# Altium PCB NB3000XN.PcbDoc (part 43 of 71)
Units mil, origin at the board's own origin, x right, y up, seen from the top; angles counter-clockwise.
Board outline 9527.56 x 6929.77 mil, 6 copper layers (Top Layer, GND+SHIELD, MidLayer1, MidLayer2, P2 - 3V3+5V0, Bottom Layer), stack 62.375 mil thick; 832 components, 1027 nets, 4655 pads, 4981 vias.
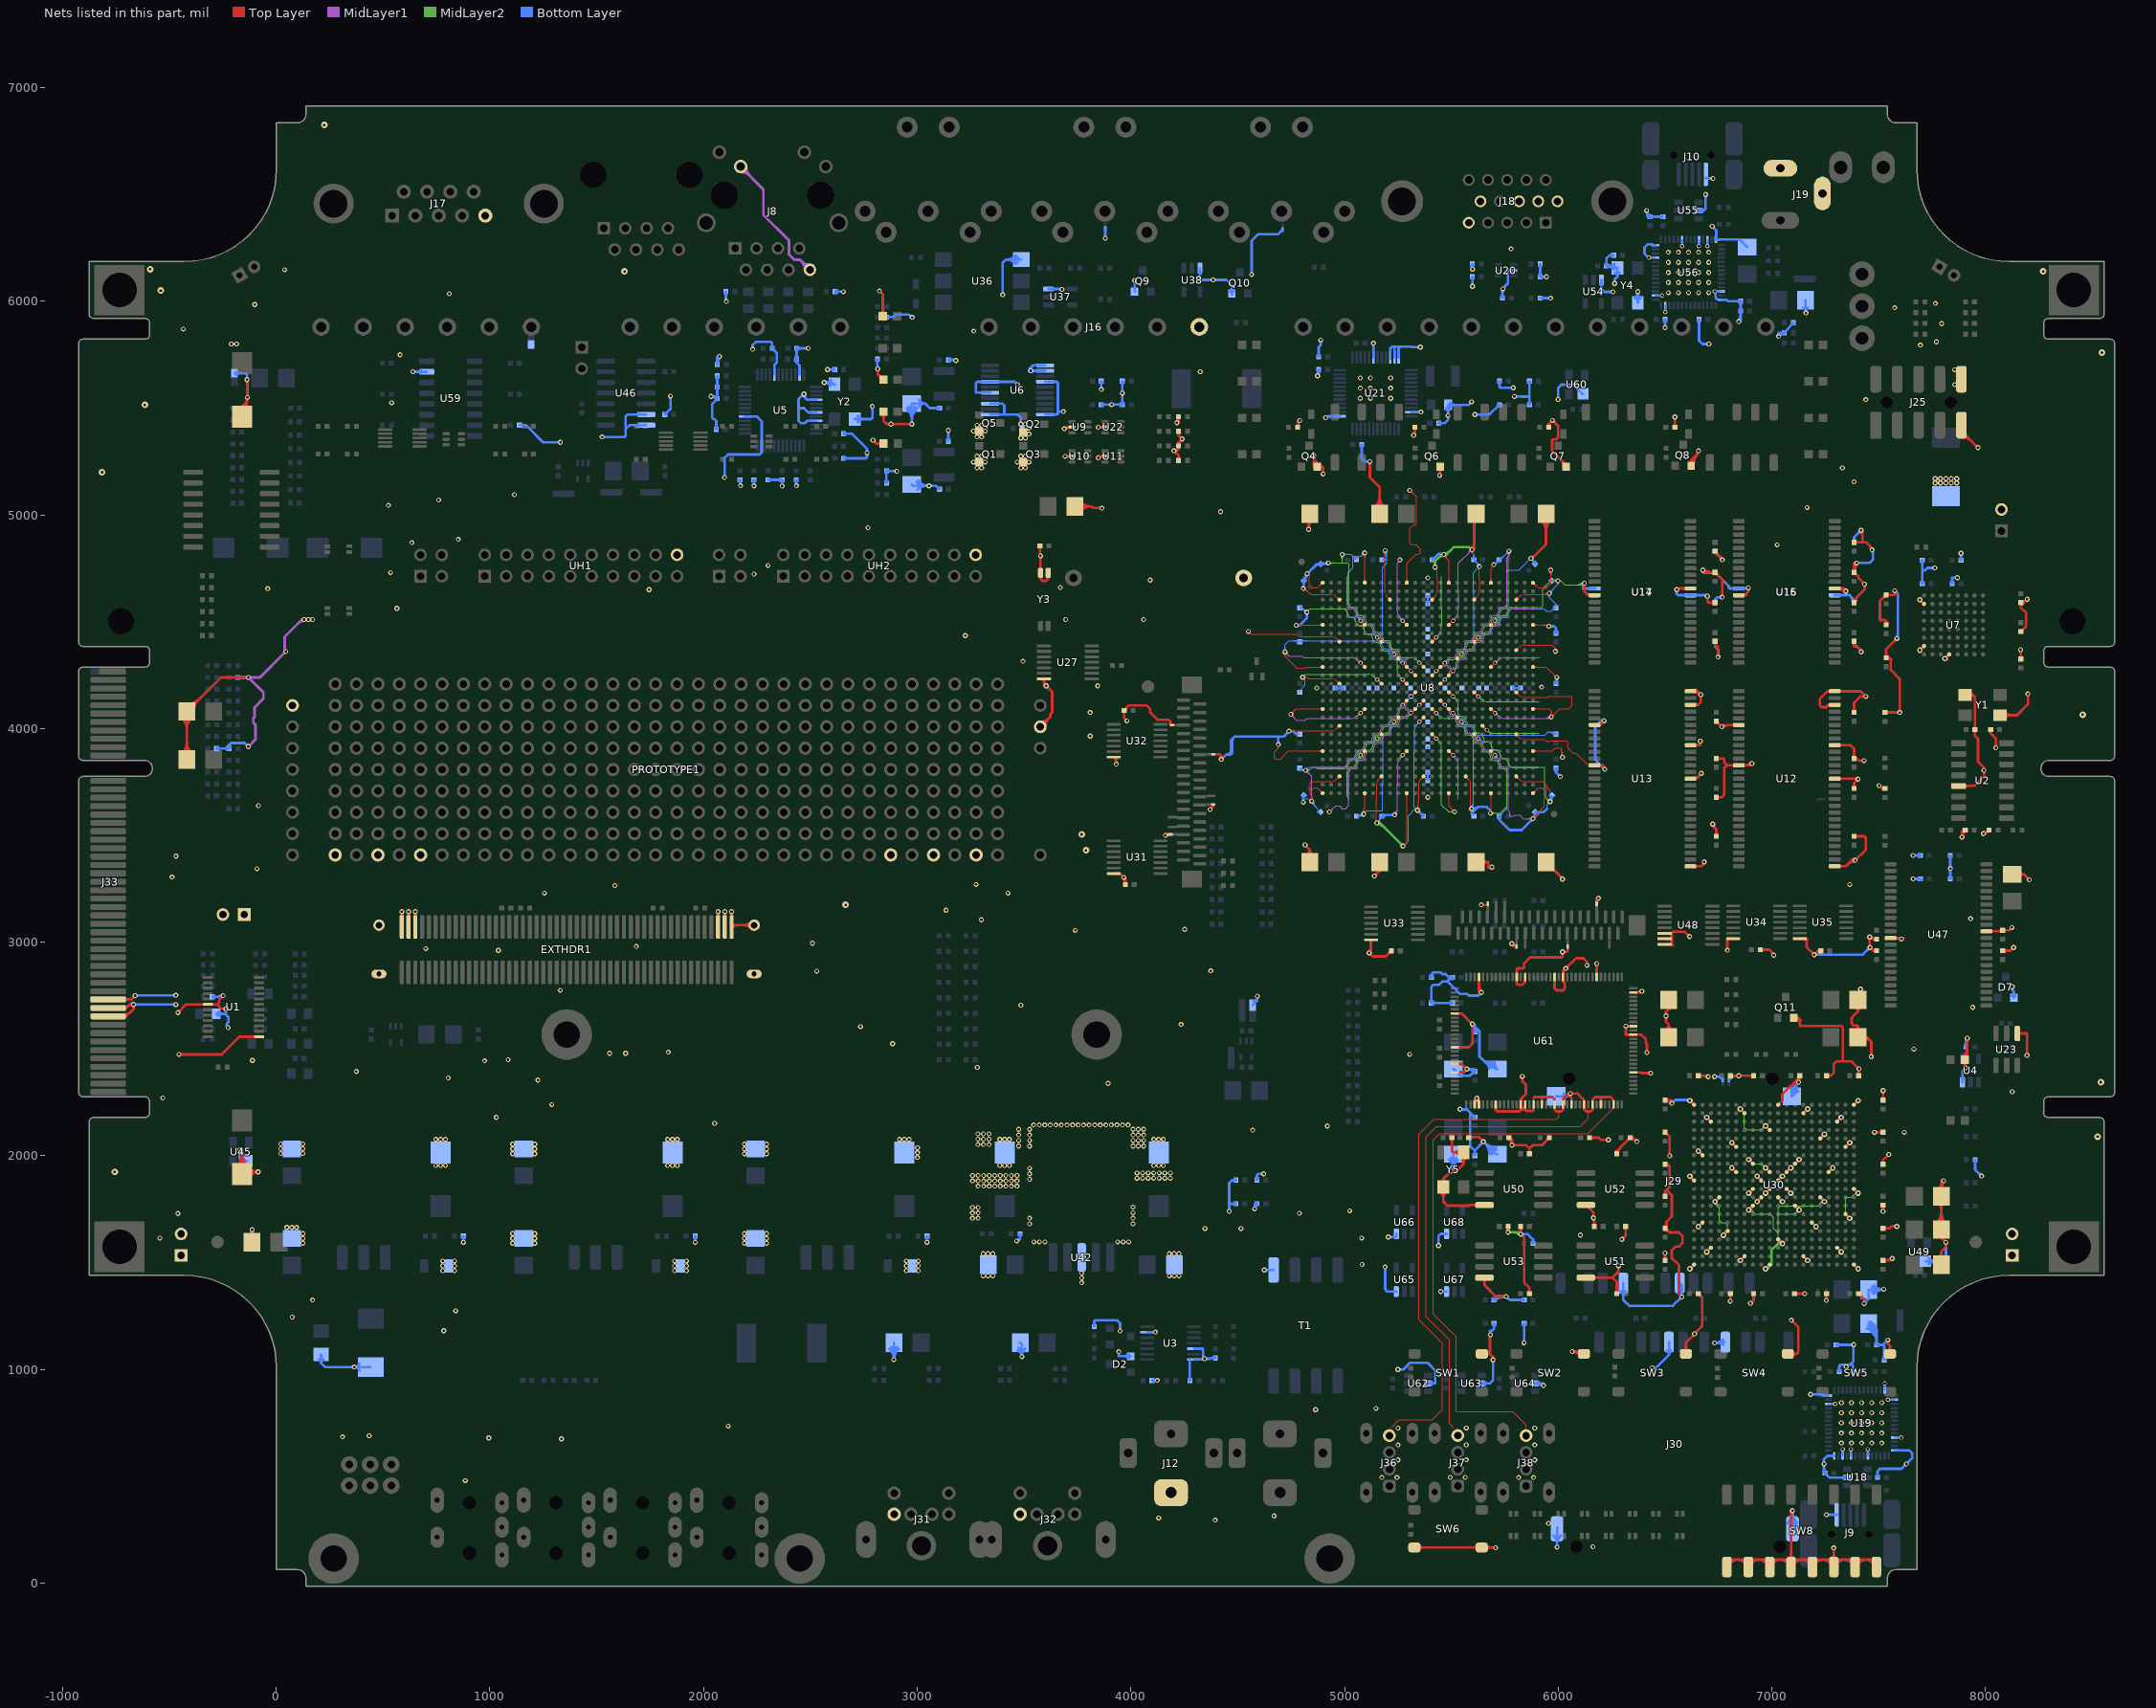
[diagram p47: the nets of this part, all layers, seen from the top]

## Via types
v1: diameter 23, hole 11.81, Top Layer to Bottom Layer, 3672 vias
v2: diameter 26, hole 11.81, Top Layer to Bottom Layer, 461 vias
v3: diameter 19, hole 11.81, Top Layer to Bottom Layer, tented both sides, 396 vias
v4: diameter 23.62, hole 11.81, Top Layer to Bottom Layer, 288 vias
v5: diameter 20, hole 11.81, Top Layer to Bottom Layer, 91 vias
v6: diameter 23, hole 11.81, Top Layer to Bottom Layer, tented both sides, 50 vias
v7: diameter 31, hole 11.81, Top Layer to Bottom Layer, 15 vias
v8: diameter 27.56, hole 11.81, Top Layer to Bottom Layer, tented both sides, 4 vias
v9: diameter 29, hole 11.81, Top Layer to Bottom Layer, 3 vias
v10: diameter 21, hole 11.81, Top Layer to Bottom Layer, 1 vias

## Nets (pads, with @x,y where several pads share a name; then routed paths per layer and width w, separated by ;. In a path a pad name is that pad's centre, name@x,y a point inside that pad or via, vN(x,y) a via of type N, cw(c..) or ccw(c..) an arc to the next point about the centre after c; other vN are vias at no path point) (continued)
GND: (continued)
  Top Layer w12: v1@7428.36,4676.04 ccw(c7415.08,4676.04) 7424.47,4685.43 ccw(c7433.86,4694.82) v1@7433.86,4681.54 ; 7428.54,110.71 cw(c7428.54,40.04) SW8.8@7478.51,90.01 ; v1@7429.97,4672.15 cw(c7420.58,4662.76) 7433.86,4662.76 cw(c7447.14,4662.76) v1@7437.75,4672.15 ; 7430.75,4159.56 cw(c7421.23,4150.04) v1@7434.69,4150.04 ; 7430.93,4159.38 ccw(c7440.19,4168.64) v1@7440.19,4155.54 ; C201.2@7435.5,2547.45 cw(c7445,2545.25) 7445,2555 ; C201.2@7435.5,2562.55 ccw(c7445,2564.75) 7445,2555 ; v1@7436.3,4146.15 ccw(c7426.91,4136.76) 7426.91,4150.04 ccw(c7426.91,4163.32) v1@7436.3,4153.93 ; v1@7453.64,3020.49 cw(c7444.25,3011.1) 7457.52,3011.1 cw(c7470.8,3011.1) v1@7461.41,3020.49 ; 7454.4,4859.83 cw(c7431.17,4836.6) v1@7464.02,4836.6 ; 7457.51,110.71 cw(c7457.51,69.01) SW8.8@7487,98.5 ; 7457.52,2992.34 ccw(c7476.49,2992.34) v1@7463.08,2978.93 ; v1@7457.73,3018.88 cw(c7458.78,2990.3) C156.2@7479,3010.52 ; v1@7461.3,2468.6 ccw(c7451.91,2477.99) 7465.19,2477.99 ccw(c7478.47,2477.99) v1@7469.08,2468.6 ; v1(7465.19,2464.71) 7465.19,2534.81 7445,2555 ; v1@7465.19,3024.33 7475.19,3014.33 C156.2@7490,3014.33 ; v1@7465.19,3024.37 v1(7457.52,3024.37) 7457.52,2976.71 v1(7459.19,2975.04) 7463.52,2975.04 7465.19,2973.37 7465.19,2969 7473.52,2960.67 C155.2@7490,2960.67 ; v1(7469.52,4836.6) 7469.52,4844.71 7442.86,4871.37 7423.52,4871.37 ; v4(7480,2110) 7479.33,2110.67 7480,2110.67 C234.2@7520,2110.67 ; v4@7484.11,2105.89 cw(c7495.64,2094.36) 7495.64,2110.67 ; v4@7484.11,2114.11 ccw(c7492.41,2122.41) 7492.41,2110.67 ; C155.2@7485.89,2956.56 ccw(c7475.97,2946.64) 7475.97,2960.67 ccw(c7475.97,2974.7) C155.2@7485.89,2964.78 ; C156.2@7485.89,3010.22 ccw(c7475.97,3000.3) 7475.97,3014.33 ccw(c7475.97,3028.36) C156.2@7485.89,3018.44 ; SW8.8@7490,110.71 7390,110.71 SW8.6@7290,110.71 ; v1(7501.86,3733.37) v1@7505.19,3730.04 ; v1@7505.19,3729.96 7515.19,3719.96 R157.1@7530,3719.96 ; v4@7515.89,1744.11 ccw(c7505.97,1754.03) 7520,1754.03 ccw(c7534.03,1754.03) v4@7524.11,1744.11 ; C195.2@7515.89,1765.22 cw(c7505.97,1755.3) 7520,1755.3 cw(c7534.03,1755.3) C195.2@7524.11,1765.22 ; C194.2@7515.89,1964.78 ccw(c7505.97,1974.7) 7520,1974.7 ccw(c7534.03,1974.7) C194.2@7524.11,1964.78 ; C234.2@7515.89,2106.56 ccw(c7505.97,2096.64) 7505.97,2110.67 ccw(c7505.97,2124.7) C234.2@7515.89,2114.78 ; C218.2@7515.89,2264.78 ccw(c7505.97,2274.7) 7520,2274.7 ccw(c7534.03,2274.7) C218.2@7524.11,2264.78 ; v4@7515.89,2300.89 cw(c7505.97,2290.97) 7520,2290.97 cw(c7534.03,2290.97) v4@7524.11,2300.89 ; C236.2@7520,1510.67 7554.82,1510.67 v1(7563.52,1519.37) ; C220.2@7520,1660.67 7549.98,1660.67 7559.31,1670 v4(7585,1670) ; v4(7520,1740) C195.2@7520,1769.33 ; C194.2@7520,1960.67 7520,1978.71 v4(7547.7,2006.4) v4@7547.7,2002.7 ; C218.2@7520,2260.67 v4(7520,2305) ; C236.2@7524.11,1506.56 cw(c7534.03,1496.64) 7534.03,1510.67 cw(c7534.03,1524.7) C236.2@7524.11,1514.78 ; C220.2@7524.11,1656.56 cw(c7534.03,1646.64) 7534.03,1660.67 cw(c7534.03,1674.7) C220.2@7524.11,1664.78 ; C58.2@7525.08,4615.75 ccw(c7515.16,4625.67) C58.2@7529.19,4625.67 ; C58.2@7525.08,4615.75 cw(c7535,4605.83) C58.2@7535,4619.86 ; R157.1@7525.75,3716.2 ccw(c7516.67,3707.12) 7516.67,3719.96 ccw(c7516.67,3732.8) R157.1@7525.75,3723.72 ; C236.2@7529.23,1510.67 ccw(c7529.23,1553.67) v1@7559.64,1523.26 ; R155.1@7530,4076.18 7578.72,4076.18 7579.86,4075.04 v1(7598.52,4075.04) 7598.52,4233.37 7556.86,4275.04 7556.86,4325 7551.19,4330.67 C60.2@7535,4330.67 7535,4371.18 v1(7585.19,4421.37) ; C60.2@7530.89,4334.78 ccw(c7520.97,4344.7) 7535,4344.7 ccw(c7549.03,4344.7) 7539.11,4334.78 ccw(c7549.03,4344.7) 7549.03,4330.67 ccw(c7549.03,4316.64) C60.2@7539.11,4326.56 ; C59.2@7530.89,4489.78 ccw(c7520.97,4499.7) 7535,4499.7 ccw(c7549.03,4499.7) C59.2@7539.11,4489.78 ; C60.2@7532,4336.08 cw(c7538.52,4324.33) 7548.03,4333.83 ; C60.2@7533.57,4336.69 cw(c7537.55,4319.91) 7549.75,4332.1 ; R155.1@7534.25,4072.42 cw(c7543.33,4063.34) 7543.33,4076.18 cw(c7543.33,4089.02) R155.1@7534.25,4079.94 ; C59.2@7535,4485.67 7535,4503.04 7529.67,4508.37 7507.19,4508.37 7506.19,4509.37 7506.19,4597.04 7521.19,4612.04 7521.56,4612.04 7521.56,4612.23 C58.2@7535,4625.67 7572.9,4625.67 7578.23,4631 ; 7536.04,4502 cw(c7522.72,4488.69) C59.2@7541.01,4484.19 ; C60.2@7537.82,4325.59 cw(c7546.55,4309.85) 7559.28,4322.58 ; C58.2@7539.11,4621.56 cw(c7549.03,4611.64) 7549.03,4625.67 cw(c7549.03,4639.7) C58.2@7539.11,4629.78 ; v4@7541.88,2006.4 cw(c7527.86,2006.4) 7537.78,1996.48 cw(c7547.7,1986.56) v4@7547.7,2000.59 ; U47.12@7555.59,3019.25 7606.86,3019.25 7615.65,3019.25 7615.65,3019.04 7615.52,3019.04 7609.19,3012.71 7606.86,3010.37 v1(7606.86,3015.04) ; v1(7575.52,4645.04) 7581.86,4638.71 7581.86,4634.71 7578.23,4631.08 ; v1@7579.69,4421.37 cw(c7566.41,4421.37) 7575.8,4411.99 cw(c7585.19,4402.6) v1@7585.19,4415.87 ; v4@7580.89,1665.89 ccw(c7570.97,1655.97) 7570.97,1670 ccw(c7570.97,1684.03) v4@7580.89,1674.11 ; 7583.41,3019.25 cw(c7583.41,2991.6) v1@7602.97,3011.15 ; v1@7594.64,4071.15 ccw(c7585.25,4061.76) 7585.25,4075.04 ccw(c7585.25,4088.32) 7594.64,4078.93 ccw(c7585.25,4088.32) 7598.52,4088.32 ccw(c7611.8,4088.32) v1@7602.41,4078.93 ; C200.2@7769.4,1682.53 ccw(c7712.43,1739.5) 7792.99,1739.5 ; C203.2@7776.12,1522.73 ccw(c7758.86,1552.17) 7792.99,1552.17 ; C190.2@7776.12,1842.73 ccw(c7758.86,1872.17) 7792.99,1872.17 ; C200.2@7777.88,1674.05 ccw(c7741.4,1710.53) 7792.99,1710.53 ccw(c7844.58,1710.53) C200.2@7808.1,1674.05 ; C190.2@7780.37,1775.17 cw(c7772.69,1756.38) 7792.99,1756.38 ; C203.2@7792.99,1490 7792.99,1552.18 ; 7792.99,1739.5 ccw(c7873.55,1739.5) C200.2@7816.59,1682.53 ; C190.2@7792.99,1843.06 cw(c7844.5,1843.06) v1@7808.08,1879.49 ; 7792.99,1872.03 cw(c7815.53,1872.03) v1@7799.59,1887.97 ; v1(7804.19,1883.37) 7792.99,1872.18 ; C190.2@7805.62,1775.17 ccw(c7813.3,1756.38) 7792.99,1756.38 ; v1@7809.69,1595.04 ccw(c7796.41,1595.04) 7805.8,1604.43 ccw(c7815.19,1613.82) v1@7815.19,1600.54 ; C203.2@7809.87,1522.73 cw(c7827.12,1552.17) 7792.99,1552.17 ; C190.2@7809.87,1842.73 cw(c7827.12,1872.17) 7792.99,1872.17 ; v1@7811.3,1591.15 cw(c7801.91,1581.76) 7815.19,1581.76 cw(c7828.47,1581.76) v1@7819.08,1591.15 ; U2.5@7874.17,3731.34 7948.52,3731.34 7992.52,3775.34 v1(7992.52,3804.71) 7992.52,3817.48 7981.46,3828.54 7981.28,3828.54 7965.19,3844.64 7965.19,3952.04 7950.86,3966.37 ; v1@7886.3,3495.6 ccw(c7876.91,3504.99) 7890.19,3504.99 ccw(c7903.47,3504.99) v1@7894.08,3495.6 ; J25.9@7886.99,5363.75 cw(c7886.99,5293.12) 7936.93,5343.07 ; J25.9@7886.99,5375.75 cw(c7886.99,5334.1) 7916.45,5363.55 ; J25.9@7886.99,5420.25 7886.99,5393.01 v4(7965,5315) ; v1@7890.19,3488.16 cw(c7926.6,3488.16) C35.2@7908.82,3519.93 ; v1@7890.19,3502.67 cw(c7906.72,3502.67) C35.2@7906.17,3519.19 ; 7890.19,3508.63 cw(c7915.14,3508.63) C35.2@7902.95,3530.4 ; 7890.19,3515.08 cw(c7906.31,3515.08) C35.2@7905.77,3531.19 ; v1@7890.52,3491.71 v1(7890.19,3491.71) 7890.19,3509.21 C35.2@7905.98,3525 ; LED1.2@7893.79,2440.32 cw(c7870.43,2416.96) 7903.47,2416.96 cw(c7936.5,2416.96) LED1.2@7913.14,2440.32 ; LED1.2@7893.79,2459.68 ccw(c7842.92,2510.54) 7914.86,2510.54 ; C35.2@7900.17,3525 cw(c7886.14,3525) 7896.06,3515.08 cw(c7905.98,3505.16) C35.2@7905.98,3519.19 ; U2.5@7901.33,3725.84 cw(c7914.61,3712.56) 7914.61,3731.34 cw(c7914.61,3750.12) U2.5@7901.33,3736.84 ; LED1.2@7902.27,2451.19 ccw(c7871.9,2481.57) 7914.86,2481.57 ; LED1.2@7903.47,2433.51 ccw(c7928.32,2433.51) v1@7910.75,2415.93 ; Y1.4@7904.88,4157.5 7940.34,4157.5 ; J25.9@7905.99,5382.75 ccw(c7927.11,5382.75) 7912.18,5367.82 ; v1(7906.86,2412.04) 7906.86,2413.37 7903.52,2416.71 7903.47,2416.71 LED1.2@7903.47,2450 7914.86,2461.39 v1(7914.86,2550.71) ; Y1.4@7907.14,4159.3 cw(c7922.84,4143.06) 7938.8,4159.03 ; Y1.4@7907.7,4159.71 cw(c7921.98,4132.88) 7943.47,4154.37 ; v1@7910.97,2546.82 cw(c7901.58,2537.43) 7914.86,2537.43 cw(c7928.14,2537.43) v1@7918.75,2546.82 ; Y1.4@7915.48,4150.67 cw(c7931.32,4134.29) 7947.43,4150.4 ; Y1.4@7928.91,4149.69 cw(c7940.33,4145.24) 7940.33,4157.5 ; Y1.4@7928.91,4165.31 ccw(c7940.33,4169.76) 7940.33,4157.5 ; C33.2@7946.56,3999.11 ccw(c7936.64,4009.03) 7950.67,4009.03 ccw(c7964.7,4009.03) C33.2@7954.78,3999.11 ; v4@7959.19,5315 ccw(c7945.16,5315) 7955.08,5324.92 ccw(c7965,5334.84) v4@7965,5320.81 ; v1@7988.64,3800.82 cw(c7979.25,3791.43) 7992.52,3791.43 cw(c8005.8,3791.43) v1@7996.41,3800.82 ; v1@7990.19,3505.04 v1(7990.19,3508.37) 8000.53,3508.37 R30.2@8017.15,3525 ; v1@7990.2,3513.87 ccw(c7990.29,3551.85) R30.2@8017.15,3525 ; U47.34@8004.41,3050.75 8075.08,3050.75 C153.2@8080,3055.67 8110.82,3055.67 v1(8123.52,3068.37) ; R30.2@8007.23,3515.08 cw(c8017.15,3505.16) R30.2@8017.15,3519.19 ; R30.2@8008.42,3516.27 ccw(c8000.18,3524.51) R30.2@8011.83,3524.51 ; C34.2@8020.22,3990.89 cw(c8010.3,3980.97) 8024.33,3980.97 cw(c8038.36,3980.97) C34.2@8028.44,3990.89 ; C34.2@8024.33,3995 8024.33,3977.37 8031.66,3970.04 8031.86,3970.04 8048.52,3953.37 v1(8048.52,3910) ; v1@8044.64,3913.89 ccw(c8035.25,3923.28) 8048.52,3923.28 ccw(c8061.8,3923.28) v1@8052.41,3913.89 ; 8054.09,3050.75 ccw(c8054.09,3081.58) C153.2@8075.89,3059.78 ; Y1.2@8067.88,4062.5 8147.5,4062.5 8198.52,4113.52 v1(8198.52,4162.37) ; C154.2@8080,2960.67 8117.49,2960.67 v1(8131.86,2975.04) ; C154.2@8084.11,2956.56 cw(c8094.03,2946.64) 8094.03,2960.67 cw(c8094.03,2974.7) C154.2@8084.11,2964.78 ; C153.2@8084.11,3051.56 cw(c8094.03,3041.64) 8094.03,3055.67 cw(c8094.03,3069.7) C153.2@8084.11,3059.78 ; Y1.2@8087.08,4047.3 cw(c8123.78,4010.59) 8123.78,4062.5 cw(c8123.78,4114.41) Y1.2@8087.08,4077.7 ; C36.2@8125,3317.99 8178.91,3317.99 ; U23.1@8151.81,2570 U23.1@8149,2572.81 8192.19,2572.81 8195,2570 v4(8195,2470) ; U23.1@8153.81,2568.01 cw(c8165.41,2556.4) 8165.41,2572.81 cw(c8165.41,2589.22) U23.1@8153.81,2577.62 ; C36.2@8159.76,3305.21 cw(c8178.9,3297.27) 8178.9,3317.99 ; C36.2@8159.76,3330.78 ccw(c8178.9,3338.72) 8178.9,3317.99 ; v1@8160.64,4365.49 cw(c8150.1,4354.95) 8165,4354.95 ; C57.2@8160.89,4329.78 ccw(c8150.97,4339.7) 8165,4339.7 ccw(c8179.03,4339.7) C57.2@8169.11,4329.78 ; C55.2@8160.89,4585.22 cw(c8150.97,4575.3) 8165,4575.3 cw(c8179.03,4575.3) 8169.11,4585.22 cw(c8179.03,4575.3) 8179.03,4589.33 cw(c8179.03,4603.36) C55.2@8169.11,4593.44 ; C55.2@8164.25,4583.19 ccw(c8166.2,4599.17) 8177.59,4587.79 ; v1(8164.52,4369.37) 8165,4370.04 8165,4369.37 C57.2@8165,4325.67 ; 8165,4357.25 cw(c8176.65,4357.25) v1@8168.41,4365.49 ; C55.2@8165.71,4595.1 ccw(c8170,4630.19) v1(8195,4605.19) 8179.14,4589.33 C55.2@8165,4589.33 8165,4566.71 8165.19,4566.71 8190.19,4541.71 8190.19,4479.37 8190.04,4479.37 8185.71,4475.04 ; C56.2@8174.82,4464 ccw(c8184.48,4454.33) 8170.81,4454.33 cw(c8184.84,4454.33) 8174.92,4464.25 cw(c8165,4474.17) 8165,4460.14 ccw(c8165,4474.53) C56.2@8175.17,4464.35 ; v4@8190.89,2474.11 ccw(c8180.97,2484.03) 8195,2484.03 ccw(c8209.03,2484.03) v4@8199.11,2474.11 ; v1@8194.64,4158.49 cw(c8185.25,4149.1) 8198.52,4149.1 cw(c8211.8,4149.1) v1@8202.41,4158.49 ; v1@8199.69,3291.71 ccw(c8186.41,3291.71) 8195.8,3301.1 ccw(c8205.19,3310.49) v1@8205.19,3297.21 ; v1(8205.19,3291.71) 8178.91,3317.99 ; -701.48,2652.86 -668.14,2686.19 v1(-668.14,2708.37) -685.48,2708.37 ; -701.48,2692.23 -701.48,2692.37 -685.48,2708.37 ; -159.72,2016.62 -159.72,1935.99 -148.78,1925.04 v1(-84.81,1925.04) ; 4223.82,5308.37 R93.1@4223.82,5323.33 4223.82,5339 v1(4240.19,5355.37) ; 4418.86,3876 4423.52,3871.33 v1(4423.52,3855.71) 4418.86,3860.37 4418.86,3876 ; Y5.2@5462.5,1855.99 5465.19,1858.68 Y5.2@5462.5,1858.68 ; Y5.2@5462.5,1855.99 Y5.2@5462.5,1858.68 ; Y5.2@5462.5,1858.68 5462.5,1892.02 ; 5462.5,1892.02 v1(5498.52,1928.04) 5523.52,1928.04 5557.5,1962.02 ; 5508.5,2016.5 Y5.4@5557.5,2016.5 5557.5,1962.02 ; U61.3@5609.37,2253.19 ccw(c5601.4,2270) v4(5620,2270) ccw(c5640.12,2270) U61.4@5629.06,2253.19 ; U61.3@5609.37,2253.19 cw(c5620,2248.92) v4@5620,2260.37 ; U61.3@5609.37,2253.19 cw(c5620,2248.92) v4@5620,2260.37 ; v4@5620,2260.37 cw(c5620,2251.08) U61.4@5629.05,2253.19 ; v4@5620,2260.37 cw(c5620,2251.08) U61.4@5629.05,2253.19 ; 5823.52,2211.95 5825.91,2214.33 ; 5823.52,2211.95 5825.91,2214.33 ; 5825.91,2214.33 5827.91,2216.33 ; 5827.91,2216.33 5843.59,2216.33 ; 5843.59,2216.33 5845.59,2214.33 ; 5845.59,2214.33 5849.54,2210.37 5881.86,2210.37 5884.96,2213.48 U61.17@5884.96,2240 5884.96,2269.81 5890.19,2275.04 5924.33,2275.04 ; 5864.6,1382.45 5865.52,1383.37 5865.67,1383.37 5865.67,1381.37 ; 5864.6,1382.45 5865.67,1381.37 ; 5865.67,2034.54 5869.84,2038.71 ; 5924.33,2275.04 5974.52,2275.04 5981.86,2267.71 5981.86,2218.24 5983.39,2216.71 ; C279.2@5943.52,3374.47 5943.52,3375 C279.2@5942.99,3375 C279.2@5943.52,3374.47 ; 5983.39,2216.71 5991.72,2208.37 6005,2208.37 6014.42,2208.37 6022.76,2216.71 ; 6022.76,2216.71 6022.76,2265.37 6049.09,2291.71 v1(6056.86,2291.71) ; 6160.55,2216.71 6160.55,2261.4 6174.19,2275.04 ; 6174.19,2275.04 6174.86,2275.71 6190.92,2275.71 6191.59,2275.04 ; 6174.19,2275.04 6191.59,2275.04 ; 6316.52,2567.57 v1@6316.52,2606.94 ; v1@6316.52,2606.94 6316.42,2606.94 v1(6316.52,2607.04) v1@6316.52,2606.94 ; 6375,2764.42 v1@6380.62,2770.04 ; 6500.19,1833.37 6506.86,1840.04 6531.86,1815.04 6531.86,1716.71 6506.86,1691.71 6506.86,1660.67 C246.2@6506.86,1658.37 ; 6500.19,1833.37 6522.19,1855.37 6522.19,1950.33 6511.86,1960.67 ; C246.2@6502.29,1658.37 C246.2@6506.86,1653.81 ; C246.2@6502.29,1658.37 C246.2@6500,1660.67 6500,1658.37 C246.2@6502.29,1658.37 ; C246.2@6502.29,1658.37 C246.2@6506.86,1658.37 ; v4(6505,2655) 6505,2672.99 6517.01,2685 ; C246.2@6506.86,1653.81 6515.19,1645.48 6515.19,1645.37 6506.86,1653.71 C246.2@6506.86,1653.81 ; C246.2@6506.86,1653.81 C246.2@6506.86,1658.37 ; 6531.97,3016.02 6531.97,3041.61 ; 6531.97,3041.61 6538.73,3048.37 ; 6622.4,5255.04 6622.52,5255.04 v1@6656.86,5289.37 ; 7123.52,2645.79 7131.86,2637.45 7131.86,2608.37 7324.86,2608.37 7331.86,2601.37 7331.86,2441.71 ; 7290.19,2390 7290.19,2430.37 7301.52,2441.71 7331.86,2441.71 ; 7331.86,2441.71 7373.52,2441.71 v1(7407.86,2407.37) v1@7413.34,2407.37 ; 7402.99,2608.37 C201.2@7402.99,2555 7445,2555 ; 7402.99,2608.37 7401.99,2609.37 7381.86,2609.37 7373.52,2617.71 7373.52,2646.37 7402.86,2675.71 7402.99,2675.71 ; C58.2@7529.19,4625.67 cw(c7515.6,4625.67) 7525.21,4616.06 ccw(c7515.6,4625.67) C58.2@7529.19,4625.67 ; C58.2@7535,4619.86 ccw(c7535,4605.39) 7524.77,4615.62 cw(c7535,4605.39) C58.2@7535,4619.86 ; 7792.99,1552.18 7815.19,1574.37 v1(7815.19,1595.04) 7792.99,1617.24 C200.2@7792.99,1655 7792.99,1755.37 7791.99,1755.37 7792.99,1756.37 ; 7792.99,1756.37 C190.2@7792.99,1810 7792.99,1872.18 ; 7940.34,4157.5 7950.67,4147.17 C33.2@7950.67,3995 ; 7950.67,3966.56 C33.2@7950.67,3995 ; 7950.67,3966.56 C33.2@7950.67,3995 ; 7950.67,3966.56 7950.67,3966.37 7950.86,3966.37 ; 7950.67,3966.56 7950.86,3966.37 ; 7950.67,3980.97 cw(c7964.7,3980.97) 7954.78,3990.89 ccw(c7964.7,3980.97) 7950.67,3980.97 ; 7950.67,3980.97 ccw(c7936.64,3980.97) 7946.56,3990.89 cw(c7936.64,3980.97) 7950.67,3980.97 ; 8185.71,4475.04 C56.2@8165,4454.33 8165,4454.18 8165.07,4454.26 8185.86,4475.04 8185.71,4475.04
  MidLayer1 w4: v1@4721.19,4348.87 cw(c4721.19,4325.94) 4737.41,4342.16 cw(c4753.63,4358.37) v1@4730.69,4358.37 ; v1@4721.19,4352.87 cw(c4721.19,4339.6) 4730.58,4348.99 cw(c4739.97,4358.37) v1@4726.69,4358.37 ; v1(4721.19,4358.37) 4741.56,4338 4802.63,4338 4808.65,4331.97 4860,4331.97 4870,4331.97 5031.66,4331.97 cw(c5031.66,4290.24) 5061.17,4319.75 ; v1@4748.52,4057.21 cw(c4748.52,4034.27) 4764.74,4050.49 cw(c4780.96,4066.71) v1@4758.02,4066.71 ; v1@4748.52,4061.21 cw(c4748.52,4047.93) 4757.91,4057.32 cw(c4767.3,4066.71) v1@4754.02,4066.71 ; v1(4748.52,4066.71) 4776.02,4039.21 4815.83,4039.21 4824.65,4048.03 4860,4048.03 4870,4048.03 4918.62,4048.03 4938.04,4048.03 5012.16,4048.03 ; v1@4817.86,3795.54 cw(c4817.86,3772.61) 4834.07,3788.82 cw(c4850.29,3805.04) v1@4827.36,3805.04 ; v1@4817.86,3799.54 cw(c4817.86,3786.26) 4827.25,3795.65 cw(c4836.64,3805.04) v1@4823.36,3805.04 ; v1@4839.47,3666.76 ccw(c4823.26,3682.98) 4846.19,3682.98 ccw(c4869.13,3682.98) v1@4852.91,3666.76 ; v1@4842.3,3663.93 ccw(c4832.91,3673.32) 4846.19,3673.32 ccw(c4859.47,3673.32) v1@4850.08,3663.93 ; v1(4846.19,3660.04) 4846.19,3776.71 v1(4817.86,3805.04) 4832.88,3820.07 4855.26,3820.07 4860,3820.07 4870,3820.07 4879.78,3820.07 4938.04,3820.07 4996.3,3820.07 ccw(c4996.3,3835.67) 5011.9,3835.67 cw(c5035.67,3835.67) 5035.67,3859.44 ccw(c5035.67,3875.04) 5051.27,3875.04 cw(c5075.04,3875.04) 5075.04,3898.81 ccw(c5075.04,3914.41) 5090.64,3914.41 cw(c5114.41,3914.41) 5114.41,3938.18 ccw(c5114.41,3953.78) 5130.01,3953.78 cw(c5153.78,3953.78) 5153.78,3977.55 ccw(c5153.78,3993.15) 5169.38,3993.15 cw(c5193.15,3993.15) 5193.15,4016.92 ccw(c5193.15,4032.52) 5208.75,4032.52 cw(c5232.52,4032.52) 5232.52,4056.29 ccw(c5232.52,4071.89) 5248.12,4071.89 cw(c5271.89,4071.89) 5271.89,4095.66 ccw(c5271.89,4111.26) 5287.49,4111.26 ; v1(4928.86,3609.71) 4929.77,3609.71 4957.94,3637.87 4977.13,3637.87 4990,3625 5005,3625 5020.07,3640.07 5020.07,3660 5020.07,3670 5020.07,3679.78 5020.07,3738.04 5020.07,3796.3 cw(c5035.67,3796.3) 5035.67,3811.9 ccw(c5035.67,3835.67) 5059.44,3835.67 cw(c5075.04,3835.67) 5075.04,3851.27 ccw(c5075.04,3875.04) 5098.81,3875.04 cw(c5114.41,3875.04) 5114.41,3890.64 ccw(c5114.41,3914.41) 5138.18,3914.41 cw(c5153.78,3914.41) 5153.78,3930.01 ccw(c5153.78,3953.78) 5177.55,3953.78 cw(c5193.15,3953.78) 5193.15,3969.38 ccw(c5193.15,3993.15) 5216.92,3993.15 cw(c5232.52,3993.15) 5232.52,4008.75 ccw(c5232.52,4032.52) 5256.29,4032.52 cw(c5271.89,4032.52) 5271.89,4048.12 ccw(c5271.89,4071.89) 5295.66,4071.89 cw(c5311.26,4071.89) 5311.26,4087.49 ; v1@4928.86,3615.21 ccw(c4928.86,3630.7) 4939.81,3619.75 ; v1@4928.86,3619.21 ccw(c4928.86,3644.36) 4946.64,3626.57 ; v1@4934.36,3609.71 cw(c4945.42,3609.71) 4937.6,3617.53 ; v1@4938.36,3609.71 cw(c4959.08,3609.71) 4944.43,3624.36 ; 4998.23,4048.03 5012.16,4048.03 ; 5011.9,4710 5011.9,4700.22 5011.9,4641.96 5011.9,4583.7 ccw(c5035.67,4583.7) 5035.67,4559.93 cw(c5035.67,4544.33) 5051.27,4544.33 ccw(c5075.04,4544.33) 5075.04,4520.56 cw(c5075.04,4504.96) 5090.64,4504.96 ccw(c5114.41,4504.96) 5114.41,4481.19 cw(c5114.41,4465.59) 5130.01,4465.59 ccw(c5153.78,4465.59) 5153.78,4441.82 cw(c5153.78,4426.22) 5169.38,4426.22 ccw(c5193.15,4426.22) 5193.15,4402.45 cw(c5193.15,4386.85) 5208.75,4386.85 ccw(c5232.52,4386.85) 5232.52,4363.08 cw(c5232.52,4347.48) 5248.12,4347.48 ccw(c5271.89,4347.48) 5271.89,4323.71 cw(c5271.89,4308.11) 5287.49,4308.11 ccw(c5311.26,4308.11) 5294.45,4291.3 5300.87,4283.57 ; v3@5067.57,4072.54 cw(c5049.53,4074.12) 5061.17,4060.25 ; v3@5067.57,4307.46 ccw(c5049.53,4305.88) 5061.17,4319.75 ; v3@5074.39,4064.42 ccw(c5072.81,4046.38) 5061.17,4060.25 ; v3@5074.39,4315.58 cw(c5072.81,4333.62) 5061.17,4319.75 ; v1@5234.52,3604.37 5248.03,3617.88 ; v1@5235.95,3596.51 cw(c5247.29,3600.25) 5238.84,3608.69 ; v1@5239.75,3597.76 cw(c5254.19,3602.53) 5243.44,3613.29 ; v1@5243.55,3599.02 cw(c5261.1,3604.81) 5248.03,3617.88 ; 5248.03,3798.23 5248.03,3812.16 ; 5248.03,4581.77 5248.03,4567.84 ; 5251.36,4775.54 ccw(c5247.01,4779.89) v1@5251.8,4783.74 ; 5253.78,4777.97 cw(c5259.19,4772.56) v1@5259.19,4780.21 ; 5254.5,4778.69 ccw(c5250.5,4782.7) v1@5254.91,4786.26 ; v1(5259.19,4789.71) 5259.19,4783.37 5248.19,4772.37 5248.03,4772.37 5248.03,4724.74 5248.03,4720 5248.03,4710 5248.03,4661.38 5248.03,4641.96 5248.03,4567.84 ; v3@5264.42,3874.39 cw(c5246.38,3872.81) 5260.25,3861.17 ; v3@5264.42,4505.61 ccw(c5246.38,4507.19) 5260.25,4518.83 ; v3@5272.54,3867.57 ccw(c5274.12,3849.53) 5260.25,3861.17 ; v3@5272.54,4512.43 cw(c5274.12,4530.47) 5260.25,4518.83 ; 5287.4,4110.75 cw(c5326.07,4110.75) 5298.73,4138.1 ; v3@5303.87,4270.04 ccw(c5286.04,4273.19) 5300.87,4283.57 ; v3@5303.92,4150.63 cw(c5286.19,4150.63) 5298.73,4138.1 ; 5310.75,4087.4 ccw(c5310.75,4126.07) 5338.1,4098.73 ; v3@5311.26,4143.29 ccw(c5311.26,4125.56) 5298.73,4138.1 ; v3@5312.56,4276.13 cw(c5315.71,4293.96) 5300.87,4283.57 ; v3@5343.29,4111.26 cw(c5325.56,4111.26) 5338.1,4098.73 ; v3@5350.63,4103.92 ccw(c5350.63,4086.19) 5338.1,4098.73 ; v3@5429.37,4276.08 ccw(c5429.37,4293.81) 5441.9,4281.27 ; v3@5436.71,4268.74 cw(c5454.44,4268.74) 5441.9,4281.27 ; v3@5467.44,4103.87 cw(c5464.29,4086.04) 5479.13,4096.43 ; v3@5468.74,4236.71 ccw(c5468.74,4254.44) 5481.27,4241.9 ; 5468.74,4292.51 ccw(c5468.74,4308.11) 5484.34,4308.11 cw(c5508.11,4308.11) 5508.11,4331.88 ccw(c5508.11,4347.48) 5523.71,4347.48 cw(c5547.48,4347.48) 5547.48,4371.25 ccw(c5547.48,4386.85) 5563.08,4386.85 cw(c5586.85,4386.85) 5586.85,4410.62 ccw(c5586.85,4426.22) 5602.45,4426.22 cw(c5626.22,4426.22) 5626.22,4449.99 ccw(c5626.22,4465.59) 5641.82,4465.59 cw(c5665.59,4465.59) 5665.59,4489.36 ccw(c5665.59,4504.96) 5681.19,4504.96 cw(c5704.96,4504.96) 5704.96,4528.73 ccw(c5704.96,4544.33) 5720.56,4544.33 cw(c5744.33,4544.33) 5744.33,4568.1 ccw(c5744.33,4583.7) 5759.93,4583.7 5759.93,4641.96 5759.93,4700.22 5759.93,4710 5759.93,4720 5759.93,4724.74 5759.93,4800 5769.86,4809.93 ; 5469.25,4292.6 ccw(c5469.25,4253.93) 5441.9,4281.27 ; v3@5476.08,4229.37 cw(c5493.81,4229.37) 5481.27,4241.9 ; v3@5476.13,4109.96 ccw(c5493.96,4106.81) 5479.13,4096.43 ; 5492.51,4268.74 cw(c5508.11,4268.74) 5508.11,4284.34 ccw(c5508.11,4308.11) 5531.88,4308.11 cw(c5547.48,4308.11) 5547.48,4323.71 ccw(c5547.48,4347.48) 5571.25,4347.48 cw(c5586.85,4347.48) 5586.85,4363.08 ccw(c5586.85,4386.85) 5610.62,4386.85 cw(c5626.22,4386.85) 5626.22,4402.45 ccw(c5626.22,4426.22) 5649.99,4426.22 cw(c5665.59,4426.22) 5665.59,4441.82 ccw(c5665.59,4465.59) 5689.36,4465.59 cw(c5704.96,4465.59) 5704.96,4481.19 ccw(c5704.96,4504.96) 5728.73,4504.96 cw(c5744.33,4504.96) 5744.33,4520.56 ccw(c5744.33,4544.33) 5768.1,4544.33 cw(c5783.7,4544.33) 5783.7,4559.93 5841.96,4559.93 5900.22,4559.93 5910,4559.93 ; 5492.6,4269.25 cw(c5453.93,4269.25) 5481.27,4241.9 ; v3@5507.46,3867.57 cw(c5505.88,3849.53) 5519.75,3861.17 ; v3@5507.46,4512.43 ccw(c5505.88,4530.47) 5519.75,4518.83 ; v3@5515.58,3874.39 ccw(c5533.62,3872.81) 5519.75,3861.17 ; v3@5515.58,4505.61 cw(c5533.62,4507.19) 5519.75,4518.83 ; 5531.97,3670 5531.97,3738.04 5531.97,3812.16 5531.97,3831.66 ccw(c5490.24,3831.66) 5519.75,3861.17 ; 5531.97,4581.77 5531.97,4567.84 ; v1@5586.69,4837.04 cw(c5563.76,4837.04) 5579.97,4820.82 cw(c5596.19,4804.61) v1@5596.19,4827.54 ; v1@5590.69,4837.04 cw(c5577.41,4837.04) 5586.8,4827.65 cw(c5596.19,4818.26) v1@5596.19,4831.54 ; v1(5596.19,4837.04) 5531.86,4772.71 5531.86,4764.49 5531.97,4764.49 5531.97,4724.74 5531.97,4720 5531.97,4710 5531.97,4661.38 5531.97,4641.96 5531.97,4567.84 ; v3@5705.61,4064.42 cw(c5707.19,4046.38) 5718.83,4060.25 ; v3@5705.61,4315.58 ccw(c5707.19,4333.62) 5718.83,4319.75 ; v3@5712.43,4072.54 ccw(c5730.47,4074.12) 5718.83,4060.25 ; v3@5712.43,4307.46 cw(c5730.47,4305.88) 5718.83,4319.75 ; v1@5763.56,4823.93 cw(c5751.14,4809.93) 5769.86,4809.93 ; v1@5766.21,4826.92 cw(c5759.02,4818.82) 5769.86,4818.82 cw(c5780.69,4818.82) v1@5773.51,4826.92 ; 5768.1,3655.26 5768.1,3658.37 ; v1(5769.86,4831.04) 5769.86,4809.93 ; v1@5776.16,4823.93 ccw(c5788.57,4809.93) 5769.86,4809.93 ; 5781.77,4048.03 5767.84,4048.03 ; 5781.77,4331.97 5767.84,4331.97 ; v1@5875.81,3571.66 ccw(c5859.59,3555.44) 5859.59,3578.37 ccw(c5859.59,3601.31) v1@5875.81,3585.09 ; v1@5878.64,3574.49 ccw(c5869.25,3565.1) 5869.25,3578.37 ccw(c5869.25,3591.65) v1@5878.64,3582.26 ; v1(5882.52,3578.37) 5836.63,3578.37 5820,3595 5799.39,3595 5794.39,3590 5775,3590 5773.03,3591.97 5773.03,3608.29 5768.1,3613.21 5768.1,3660 5768.1,3670 ; 5910,4331.97 5861.38,4331.97 5841.96,4331.97 5767.84,4331.97 ; 5931.21,4048.03 ccw(c5931.21,4090.36) v1@5961.14,4060.43 ; 5940.86,4048.03 ccw(c5940.86,4080.7) v1@5963.97,4057.6 ; 5950.52,4048.03 ccw(c5950.52,4071.04) v1@5966.8,4054.77 ; v1(5967.86,4053.71) 5962.18,4048.03 5924.74,4048.03 5920,4048.03 5910,4048.03 5861.38,4048.03 5841.96,4048.03 5767.84,4048.03 ; 5012.16,4048.03 5031.66,4048.03 ccw(c5031.66,4089.76) 5061.17,4060.25 ; 5248.03,3617.88 5248.03,3655.26 5248.03,3660 5248.03,3670 5248.03,3718.62 5248.03,3738.04 5248.03,3812.16 ; 5248.03,3812.16 5248.03,3831.66 cw(c5289.76,3831.66) 5260.25,3861.17 ; 5248.03,4567.84 5248.03,4548.34 ccw(c5289.76,4548.34) 5260.25,4518.83 ; 5479.13,4096.43 5485.55,4088.7 cw(c5468.74,4071.89) 5492.51,4071.89 ccw(c5508.11,4071.89) 5508.11,4056.29 cw(c5508.11,4032.52) 5531.88,4032.52 ccw(c5547.48,4032.52) 5547.48,4016.92 cw(c5547.48,3993.15) 5571.25,3993.15 ccw(c5586.85,3993.15) 5586.85,3977.55 cw(c5586.85,3953.78) 5610.62,3953.78 ccw(c5626.22,3953.78) 5626.22,3938.18 cw(c5626.22,3914.41) 5649.99,3914.41 ccw(c5665.59,3914.41) 5665.59,3898.81 cw(c5665.59,3875.04) 5689.36,3875.04 ccw(c5704.96,3875.04) 5704.96,3859.44 cw(c5704.96,3835.67) 5728.73,3835.67 ccw(c5744.33,3835.67) 5744.33,3820.07 cw(c5744.33,3796.3) 5768.1,3796.3 5768.1,3738.04 5768.1,3710 ; 5519.75,4518.83 ccw(c5490.24,4548.34) 5531.97,4548.34 5531.97,4567.84 ; 5718.83,4060.25 ccw(c5748.34,4089.76) 5748.34,4048.03 5767.84,4048.03 ; 5718.83,4319.75 cw(c5748.34,4290.24) 5748.34,4331.97 5767.84,4331.97 ; 5768.1,3670 5768.1,3710 ; 5768.1,3670 5768.1,3679.78 5768.1,3710
  MidLayer1 w12: v1(-130.48,3915.37) -96.64,3949.21 -96.64,4017.28 -97.54,4018.18 ; v1@-130.48,3920.87 ccw(c-130.48,3934.15) -121.09,3924.76 ccw(c-111.7,3915.37) v1@-124.98,3915.37 ; v1@-130.48,4233.87 cw(c-130.48,4220.6) -121.09,4229.99 cw(c-111.7,4239.37) v1@-124.98,4239.37 ; v1@-126.59,4235.49 cw(c-117.2,4226.1) -117.2,4239.37 cw(c-117.2,4252.65) v1@-126.59,4243.26 ; -97.41,4018.31 -106.5,4027.4 -106.5,4048.91 -101.5,4053.91 -101.5,4098.91 -60,4140.41 -60,4168.9 v1(-130.48,4239.37) -75.63,4239.37 40,4355 40,4430 120,4510 v4(130,4510) v4(150,4510) v4(170,4510) ; 103.01,4493.01 cw(c130,4466.02) v4@130,4504.19 ; v4@134.11,4505.89 cw(c144.03,4495.97) 144.03,4510 cw(c144.03,4524.03) v4@134.11,4514.11 ; v4@145.89,4505.89 ccw(c135.97,4495.97) 135.97,4510 ccw(c135.97,4524.03) v4@145.89,4514.11 ; v4@154.11,4505.89 cw(c164.03,4495.97) 164.03,4510 cw(c164.03,4524.03) v4@154.11,4514.11 ; v4@165.89,4505.89 ccw(c155.97,4495.97) 155.97,4510 ccw(c155.97,4524.03) v4@165.89,4514.11 ; J8.10@2173.98,6604.67 cw(c2173.98,6542.17) 2218.18,6586.37 cw(c2262.38,6630.56) J8.10@2199.87,6630.56 ; J8.10@2173.98,6616.67 cw(c2173.98,6583.14) 2197.7,6606.85 cw(c2221.41,6630.56) J8.10@2187.87,6630.56 ; J8.10@2173.98,6630.56 2280,6524.55 2280,6405 2400,6285 2400,6219.54 2425,6194.54 2450.95,6194.54 J8.8@2498,6147.49 ; J8.8@2474.47,6147.49 ccw(c2417.67,6147.49) 2457.84,6187.66 ccw(c2498,6227.82) J8.8@2498,6171.02 ; v1(5234.52,3596.04) v1@5234.52,3604.37 ; v1(6683.52,3375.71) v1@6687.52,3379.71 ; v1(6766.19,4008.37) v1@6772.19,4008.37 ; v1@8125.19,2968.37 v1(8131.86,2975.04)
  MidLayer2 w4: v1(4803.86,4240.37) 4816.71,4253.23 4856.86,4253.23 ; v1(4823.52,4544.71) 4838.75,4559.93 4855.26,4559.93 4860,4559.93 4870,4559.93 4879.78,4559.93 4938.04,4559.93 4996.3,4559.93 cw(c4996.3,4544.33) 5011.9,4544.33 ccw(c5035.67,4544.33) 5035.67,4520.56 cw(c5035.67,4504.96) 5051.27,4504.96 ccw(c5075.04,4504.96) 5075.04,4481.19 cw(c5075.04,4465.59) 5090.64,4465.59 ccw(c5114.41,4465.59) 5114.41,4441.82 cw(c5114.41,4426.22) 5130.01,4426.22 ccw(c5153.78,4426.22) 5153.78,4402.45 cw(c5153.78,4386.85) 5169.38,4386.85 ccw(c5193.15,4386.85) 5193.15,4363.08 cw(c5193.15,4347.48) 5208.75,4347.48 ccw(c5232.52,4347.48) 5232.52,4323.71 cw(c5232.52,4308.11) 5248.12,4308.11 ; v1(4846.19,3660.04) v1@4847.74,3661.59 ; 4855.26,4253.23 4860,4253.23 4870,4253.23 4997.36,4253.23 5016.78,4253.23 5090.9,4253.23 5110.4,4253.23 cw(c5110.4,4211.5) 5139.91,4241.01 ; 4870,3811.9 4879.78,3811.9 4938.04,3811.9 4996.3,3811.9 ccw(c4996.3,3835.67) 5020.07,3835.67 cw(c5035.67,3835.67) 5035.67,3851.27 ccw(c5035.67,3875.04) 5059.44,3875.04 cw(c5075.04,3875.04) 5075.04,3890.64 ccw(c5075.04,3914.41) 5098.81,3914.41 cw(c5114.41,3914.41) 5114.41,3930.01 ccw(c5114.41,3953.78) 5138.18,3953.78 cw(c5153.78,3953.78) 5153.78,3969.38 ccw(c5153.78,3993.15) 5177.55,3993.15 cw(c5193.15,3993.15) 5193.15,4008.75 ccw(c5193.15,4032.52) 5216.92,4032.52 cw(c5232.52,4032.52) 5232.52,4048.12 ccw(c5232.52,4071.89) 5256.29,4071.89 5256.29,4091.45 ; v1(4924.52,4775.04) 4988.86,4775.04 ; v1@4928.41,4771.15 cw(c4937.8,4761.76) 4937.8,4775.04 cw(c4937.8,4788.32) v1@4928.41,4778.93 ; v1@4931.24,4768.32 cw(c4947.46,4752.11) 4947.46,4775.04 cw(c4947.46,4797.98) v1@4931.24,4781.76 ; v1@4982.14,4808.32 cw(c4965.92,4792.11) 4988.86,4792.11 cw(c5011.79,4792.11) v1@4995.57,4808.32 ; v1@4984.97,4811.15 cw(c4975.58,4801.76) 4988.86,4801.76 cw(c5002.14,4801.76) v1@4992.75,4811.15 ; v1(4988.86,4815.04) 4988.86,4775.04 ; 5011.9,3679.78 5011.9,3738.04 5011.9,3796.3 cw(c5035.67,3796.3) 5035.67,3820.07 ccw(c5035.67,3835.67) 5051.27,3835.67 cw(c5075.04,3835.67) 5075.04,3859.44 ccw(c5075.04,3875.04) 5090.64,3875.04 cw(c5114.41,3875.04) 5114.41,3898.81 ccw(c5114.41,3914.41) 5130.01,3914.41 cw(c5153.78,3914.41) 5153.78,3938.18 ccw(c5153.78,3953.78) 5169.38,3953.78 cw(c5193.15,3953.78) 5193.15,3977.55 ccw(c5193.15,3993.15) 5208.75,3993.15 cw(c5232.52,3993.15) 5232.52,4016.92 ccw(c5232.52,4032.52) 5248.12,4032.52 ; v3@5146.31,4228.72 ccw(c5128.27,4227.14) 5139.91,4241.01 ; v3@5153.13,4236.84 cw(c5151.55,4254.88) 5139.91,4241.01 ; 5248.03,4308.02 5248.03,4269.25 ccw(c5286.7,4269.25) 5259.36,4241.9 ; 5255.08,4049.33 ccw(c5271.89,4032.52) 5248.12,4032.52 ; 5256.38,4091.55 cw(c5266.53,4091.55) 5259.36,4098.73 ; v3@5264.55,4111.26 cw(c5246.82,4111.26) 5259.36,4098.73 ; v3@5264.55,4229.37 ccw(c5246.82,4229.37) 5259.36,4241.9 ; v3@5271.89,4103.92 ccw(c5271.89,4086.19) 5259.36,4098.73 ; v3@5271.89,4236.71 cw(c5271.89,4254.44) 5259.36,4241.9 ; 5271.98,4331.97 5310.75,4331.97 cw(c5310.75,4293.3) 5338.1,4320.64 ; 5291.45,4056.29 5271.89,4056.29 ccw(c5271.89,4032.52) 5248.12,4032.52 ; 5291.55,4056.38 ccw(c5291.55,4066.53) 5298.73,4059.36 ; v3@5343.29,4308.11 ccw(c5325.56,4308.11) 5338.1,4320.64 ; v3@5350.63,4315.45 cw(c5350.63,4333.18) 5338.1,4320.64 ; v1(5423.52,4755.71) v1@5426.19,4758.37 ; v3@5428.72,3946.31 cw(c5427.14,3928.27) 5441.01,3939.91 ; v3@5428.72,4433.69 ccw(c5427.14,4451.73) 5441.01,4440.09 ; v3@5429.37,4064.55 cw(c5429.37,4046.82) 5441.9,4059.36 ; v3@5436.71,4071.89 ccw(c5454.44,4071.89) 5441.9,4059.36 ; v3@5436.84,3953.13 ccw(c5454.88,3951.55) 5441.01,3939.91 ; v3@5436.84,4426.87 cw(c5454.88,4428.45) 5441.01,4440.09 ; 5453.23,4710 5453.23,4582.64 5453.23,4563.22 5453.23,4489.1 5453.23,4469.6 cw(c5411.5,4469.6) 5441.01,4440.09 ; 5453.23,4813.08 5456.86,4816.71 5458.56,4815 v1(5465,4815) ; 5488.45,4323.62 ccw(c5488.45,4313.47) 5481.27,4320.64 ; 5488.55,4323.71 5508.11,4323.71 ccw(c5508.11,4347.48) 5531.88,4347.48 ; 5508.02,4048.03 5469.25,4048.03 cw(c5469.25,4086.7) 5441.9,4059.36 ; v3@5508.11,4143.29 cw(c5508.11,4125.56) 5520.64,4138.1 ; v3@5508.11,4276.08 ccw(c5508.11,4293.81) 5520.64,4281.27 ; v1@5508.28,3603.28 ccw(c5492.06,3587.06) 5492.06,3610 ccw(c5492.06,3632.93) v1@5508.28,3616.72 ; v1@5511.11,3606.11 ccw(c5501.72,3596.72) 5501.72,3610 ccw(c5501.72,3623.28) v1@5511.11,3613.89 ; v1(5515,3610) 5486.31,3610 5453.23,3643.08 5453.23,3660 5453.23,3670 5453.23,3797.36 5453.23,3816.78 5453.23,3890.9 5453.23,3910.4 ccw(c5411.5,3910.4) 5441.01,3939.91 ; v3@5515.45,4150.63 ccw(c5533.18,4150.63) 5520.64,4138.1 ; v3@5515.45,4268.74 cw(c5533.18,4268.74) 5520.64,4281.27 ; 5523.62,4288.45 cw(c5513.47,4288.45) 5520.64,4281.27 ; 5523.71,4288.55 5523.71,4308.11 cw(c5547.48,4308.11) 5547.48,4331.88 ccw(c5547.48,4347.48) 5563.08,4347.48 cw(c5586.85,4347.48) 5586.85,4371.25 ccw(c5586.85,4386.85) 5602.45,4386.85 cw(c5626.22,4386.85) 5626.22,4410.62 ccw(c5626.22,4426.22) 5641.82,4426.22 cw(c5665.59,4426.22) 5665.59,4449.99 ccw(c5665.59,4465.59) 5681.19,4465.59 cw(c5704.96,4465.59) 5704.96,4489.36 ccw(c5704.96,4504.96) 5720.56,4504.96 cw(c5744.33,4504.96) 5744.33,4528.73 ccw(c5744.33,4544.33) 5759.93,4544.33 cw(c5783.7,4544.33) 5783.7,4568.1 5841.96,4568.1 5900.22,4568.1 5910,4568.1 5920,4568.1 ; 5524.92,4330.67 ccw(c5508.11,4347.48) 5531.88,4347.48 ; 5531.88,4071.89 ccw(c5547.48,4071.89) 5547.48,4056.29 cw(c5547.48,4032.52) 5571.25,4032.52 ccw(c5586.85,4032.52) 5586.85,4016.92 cw(c5586.85,3993.15) 5610.62,3993.15 ccw(c5626.22,3993.15) 5626.22,3977.55 cw(c5626.22,3953.78) 5649.99,3953.78 ccw(c5665.59,3953.78) 5665.59,3938.18 cw(c5665.59,3914.41) 5689.36,3914.41 ccw(c5704.96,3914.41) 5704.96,3898.81 cw(c5704.96,3875.04) 5728.73,3875.04 ccw(c5744.33,3875.04) 5744.33,3859.44 cw(c5744.33,3835.67) 5768.1,3835.67 ccw(c5783.7,3835.67) 5783.7,3820.07 5841.96,3820.07 5900.22,3820.07 5910,3820.07 5920,3820.07 5924.74,3820.07 5935.19,3820.07 5936.86,3818.4 5936.86,3683.04 v1(5961.52,3658.37) ; 5531.97,4071.98 5531.97,4110.75 ccw(c5493.3,4110.75) 5520.64,4138.1 ; v3@5626.87,4143.16 cw(c5628.45,4125.12) 5640.09,4138.99 ; v3@5633.69,4151.28 ccw(c5651.73,4152.86) 5640.09,4138.99 ; v3@5666.24,3985.68 cw(c5667.82,3967.64) 5679.46,3981.51 cw(c5691.1,3995.38) v3@5673.06,3993.8 ; 5679.17,3981.76 ccw(c5689.1,3991.69) 5689.1,3977.64 5782.64,3977.64 5910,3977.64 ; v1(5682.52,3603.71) 5728.71,3603.71 5759.93,3634.93 5759.93,3655.26 5759.93,3660 5759.93,3670 5759.93,3679.78 5759.93,3738.04 5759.93,3796.3 ccw(c5744.33,3796.3) 5744.33,3811.9 cw(c5744.33,3835.67) 5720.56,3835.67 ccw(c5704.96,3835.67) 5704.96,3851.27 cw(c5704.96,3875.04) 5681.19,3875.04 ccw(c5665.59,3875.04) 5665.59,3890.64 cw(c5665.59,3914.41) 5641.82,3914.41 ccw(c5626.22,3914.41) 5626.22,3930.01 cw(c5626.22,3953.78) 5602.45,3953.78 ccw(c5586.85,3953.78) 5586.85,3969.38 cw(c5586.85,3993.15) 5563.08,3993.15 ccw(c5547.48,3993.15) 5547.48,4008.75 cw(c5547.48,4032.52) 5523.71,4032.52 ; v1@5686.41,3599.82 cw(c5695.8,3590.43) 5695.8,3603.71 cw(c5695.8,3616.99) v1@5686.41,3607.6 ; v1@5689.24,3596.99 cw(c5705.46,3580.77) 5705.46,3603.71 cw(c5705.46,3626.64) v1@5689.24,3610.43 ; v1@5763.14,4824.32 cw(c5751.16,4812.35) 5768.1,4812.35 ; 5768.1,4803.87 cw(c5797.03,4803.87) v1@5776.57,4824.32 ; 5768.1,4813.52 cw(c5787.37,4813.52) v1@5773.75,4827.15 ; v1(5769.86,4831.04) 5768.1,4829.28 5768.1,4724.74 5768.1,4720 5768.1,4710 5768.1,4700.22 5768.1,4641.96 5768.1,4583.7 cw(c5744.33,4583.7) 5744.33,4559.93 ccw(c5744.33,4544.33) 5728.73,4544.33 cw(c5704.96,4544.33) 5704.96,4520.56 ccw(c5704.96,4504.96) 5689.36,4504.96 cw(c5665.59,4504.96) 5665.59,4481.19 ccw(c5665.59,4465.59) 5649.99,4465.59 cw(c5626.22,4465.59) 5626.22,4441.82 ccw(c5626.22,4426.22) 5610.62,4426.22 cw(c5586.85,4426.22) 5586.85,4402.45 ccw(c5586.85,4386.85) 5571.25,4386.85 cw(c5547.48,4386.85) 5547.48,4363.08 ccw(c5547.48,4347.48) 5531.88,4347.48 ; 5910,4126.77 5782.64,4126.77 5763.22,4126.77 5689.1,4126.77 5669.6,4126.77 cw(c5669.6,4168.5) 5640.09,4138.99 ; 5924.74,4568.1 5920,4568.1 ; v1@5952.02,3658.37 ccw(c5929.09,3658.37) 5945.31,3674.59 ccw(c5961.52,3690.81) v1@5961.52,3667.87 ; v1@5956.02,3658.37 ccw(c5942.75,3658.37) 5952.13,3667.76 ccw(c5961.52,3677.15) v1@5961.52,3663.87 ; v1@5958.47,4735.99 cw(c5942.26,4719.77) 5965.19,4719.77 cw(c5988.13,4719.77) v1@5971.91,4735.99 ; v1@5961.3,4738.82 cw(c5951.91,4729.43) 5965.19,4729.43 cw(c5978.47,4729.43) v1@5969.08,4738.82 ; v1(5965.19,4742.71) 5965.19,4691.71 ; v1@5991.81,4684.99 ccw(c5975.59,4668.77) 5975.59,4691.71 ccw(c5975.59,4714.64) v1@5991.81,4698.43 ; v1@5994.64,4687.82 ccw(c5985.25,4678.43) 5985.25,4691.71 ccw(c5985.25,4704.99) v1@5994.64,4695.6 ; 6078.67,4672.04 ccw(c6078.67,4724.57) v1@6115.81,4687.43 ; 6088.32,4672.04 ccw(c6088.32,4714.91) v1@6118.64,4684.6 ; 6097.98,4672.04 ccw(c6097.98,4705.25) v1@6121.46,4681.77 ; 6107.64,4672.04 ccw(c6107.64,4695.6) v1@6124.29,4678.94 ; v1(6122.52,4680.71) 6113.86,4672.04 6031.86,4672.04 6012.19,4691.71 v1(5998.52,4691.71) 5965.19,4691.71 ; 4988.86,4775.04 5015,4775.04 5020.19,4769.85 5020.19,4733.37 5020.07,4733.37 5020.07,4724.74 5020.07,4720 5020.07,4710 5020.07,4700.22 5020.07,4641.96 5020.07,4583.7 ccw(c5035.67,4583.7) 5035.67,4568.1 cw(c5035.67,4544.33) 5059.44,4544.33 ccw(c5075.04,4544.33) 5075.04,4528.73 cw(c5075.04,4504.96) 5098.81,4504.96 ccw(c5114.41,4504.96) 5114.41,4489.36 cw(c5114.41,4465.59) 5138.18,4465.59 ccw(c5153.78,4465.59) 5153.78,4449.99 cw(c5153.78,4426.22) 5177.55,4426.22 ccw(c5193.15,4426.22) 5193.15,4410.62 cw(c5193.15,4386.85) 5216.92,4386.85 ccw(c5232.52,4386.85) 5232.52,4371.25 cw(c5232.52,4347.48) 5256.29,4347.48 ; 5256.29,4347.48 ccw(c5271.89,4347.48) 5271.89,4331.88 cw(c5271.89,4347.48) 5256.29,4347.48 ; 5298.73,4059.36 cw(c5311.26,4046.82) 5311.26,4064.55 ccw(c5311.26,4046.82) 5298.73,4059.36 ; 5298.73,4059.36 ccw(c5286.19,4071.89) 5303.92,4071.89 cw(c5286.19,4071.89) 5298.73,4059.36 ; 5481.27,4320.64 ccw(c5493.81,4308.11) 5476.08,4308.11 cw(c5493.81,4308.11) 5481.27,4320.64 ; 5481.27,4320.64 cw(c5468.74,4333.18) 5468.74,4315.45 ccw(c5468.74,4333.18) 5481.27,4320.64 ; 5523.71,4032.52 ccw(c5508.11,4032.52) 5508.11,4048.12 cw(c5508.11,4032.52) 5523.71,4032.52 ; 5920,4568.1 5925.29,4568.1 5929.19,4572 5929.19,4655.71 ; 5929.19,4655.71 5950.66,4677.17 ; 5929.19,4655.71 5950.66,4677.17 ; 5929.19,4655.71 5961.7,4688.22 ; 5950.66,4677.17 5961.7,4688.22 ; 5950.66,4677.17 5961.7,4688.22 ; 5961.7,4688.22 5965.19,4691.71 ; 5961.7,4688.22 5965.19,4691.71
  MidLayer2 w5: v2(6734.41,1786.26) 6734.41,1774.47 6754.28,1754.6 6754.28,1699.44 6765.7,1688.02 6781.49,1688.02 6793.28,1676.23 6793.28,1658.28 ; v2@6734.87,1786.07 ccw(c6747.56,1780.76) 6737.84,1771.04 ; v2@6739.48,1784.14 ccw(c6755,1777.66) 6743.11,1765.77 ; v2@6744.1,1782.21 ccw(c6762.44,1774.55) 6748.38,1760.49 ; v2(6773.78,1628.78) 6773.78,1638.78 6793.28,1658.28 ; v2@6774.27,1628.86 cw(c6792.07,1631.61) 6779.34,1644.34 ; v2@6779.22,1629.62 cw(c6804.14,1633.47) 6786.31,1651.31 ; v2@6784.16,1630.38 cw(c6816.22,1635.34) 6793.28,1658.28 ; v2@6852.52,2208.83 cw(c6852.52,2183.48) 6870.44,2201.41 cw(c6888.37,2219.33) v2@6863.02,2219.33 ; v2@6852.52,2213.83 cw(c6852.52,2200.55) 6861.91,2209.94 cw(c6871.3,2219.33) v2@6858.02,2219.33 ; v2(6852.52,2219.33) 6872.02,2199.83 6872.02,2132.88 6883.81,2121.09 6951.13,2121.09 v2(6970.63,2140.59) ; v2(6891.89,1746.89) 6903.68,1746.89 6923.18,1727.39 6992.61,1727.39 7006.8,1713.2 7006.8,1659.56 7029.87,1636.49 ; v2@6891.89,1972.61 cw(c6891.89,1947.26) 6909.81,1965.19 cw(c6927.74,1983.11) v2@6902.39,1983.11 ; v2@6891.89,1977.61 cw(c6891.89,1964.33) 6901.28,1973.72 cw(c6910.67,1983.11) v2@6897.39,1983.11 ; v2(6891.89,1983.11) 6911.39,1963.61 6950.76,1963.61 v2(6970.63,1943.74) ; v2@6891.9,1746.39 cw(c6892.45,1718.09) 6912.47,1738.1 ; v2@6892,1741.39 cw(c6892.77,1701.8) 6920.77,1729.8 ; v2@6960.13,1943.74 ccw(c6934.78,1943.74) 6952.71,1961.66 ccw(c6970.63,1979.59) v2@6970.63,1954.24 ; v2@6960.13,2140.59 cw(c6934.78,2140.59) 6952.71,2122.67 cw(c6970.63,2104.74) v2@6970.63,2130.09 ; v2@6965.13,1943.74 ccw(c6951.85,1943.74) 6961.24,1953.13 ccw(c6970.63,1962.52) v2@6970.63,1949.24 ; v2@6965.13,2140.59 cw(c6951.85,2140.59) 6961.24,2131.2 cw(c6970.63,2121.81) v2@6970.63,2135.09 ; v2@7038.87,1589.41 ccw(c7013.52,1589.41) 7031.45,1607.33 ccw(c7049.37,1625.26) v2@7049.37,1599.91 ; v2@7043.87,1589.41 ccw(c7030.59,1589.41) 7039.98,1598.8 ccw(c7049.37,1608.19) v2@7049.37,1594.91 ; v2(7049.37,1589.41) 7048.78,1590 7029.87,1608.91 7029.87,1636.49 ; v2@7117.61,1746.89 cw(c7092.26,1746.89) 7110.19,1728.97 cw(c7128.11,1711.04) v2@7128.11,1736.39 ; v2@7122.61,1746.89 cw(c7109.33,1746.89) 7118.72,1737.5 cw(c7128.11,1728.11) v2@7128.11,1741.39 ; v2(7128.11,1746.89) 7108.61,1727.39 7032.48,1727.39 7029.87,1730 ; 7217.34,1769.17 cw(c7245.34,1741.17) v2@7246.11,1780.76 ; 7225.64,1777.47 cw(c7245.66,1757.46) v2@7246.21,1785.76 ; v2(7246.22,1786.26) 7234.43,1786.26 7214.93,1766.76 7041.66,1766.76 7029.87,1754.97 7029.87,1730 ; v2@7353.83,1707.52 ccw(c7328.48,1707.52) 7346.41,1725.44 ccw(c7364.33,1743.37) v2@7364.33,1718.02 ; v2@7358.83,1707.52 ccw(c7345.55,1707.52) 7354.94,1716.91 ccw(c7364.33,1726.3) v2@7364.33,1713.02 ; v2(7364.33,1707.52) 7345,1726.85 7345,1738.64 7344.83,1738.81 7344.83,1804.83 7346.13,1806.13 7372.41,1806.13 7391.91,1825.63 v2@7394.22,1825.63 ; 7029.87,1636.49 7029.87,1730
  MidLayer2 w8: v2@7394.22,1825.63 v2(7403.7,1825.63)
  MidLayer2 w12: v1@5150.86,3552.87 cw(c5150.86,3504.99) 5184.71,3538.85 ; v1(5150.86,3558.37) 5165.19,3558.37 v1(5273.52,3450.04) ; v1@5150.86,3564.87 cw(c5150.86,3545.96) 5164.23,3559.34 ; v1@5268.02,3450.04 ccw(c5254.75,3450.04) 5264.14,3459.43 ccw(c5273.52,3468.82) v1@5273.52,3455.54 ; v1@5419.64,4759.6 ccw(c5410.25,4768.99) 5423.52,4768.99 ccw(c5436.8,4768.99) v1@5427.41,4759.6 ; v1(5423.52,4755.71) 5423.52,4783.37 5456.86,4816.71 5479.89,4816.71 5513.18,4850 5583.23,4850 v1(5596.19,4837.04) ; 5438.79,4798.65 cw(c5465,4772.44) v1@5465,4809.5 ; v1@5465,4808.5 ccw(c5465,4824.62) 5476.4,4813.22 ; v1@5465,4820.5 ccw(c5465,4865.59) 5496.89,4833.71 ; v1(5765.34,1642.37) 5816.19,1642.37 v1(5825.19,1633.37) ; v1@5769.22,1638.49 cw(c5778.61,1629.1) 5778.61,1642.37 cw(c5778.61,1655.65) v1@5769.22,1646.26 ; 5790.18,1642.37 cw(c5790.18,1598.37) v1@5821.3,1629.49 ; v4(6020,2955) v4@6020,2960 ; v2(6970.63,1471.3) 6965.19,1471.3 6965.19,1475.04 6981.86,1475.04 6998.52,1491.71 6998.52,1558.37 7030.15,1590 7048.78,1590 v2@7050,1590 ; v2@6970.63,1478.3 ccw(c6970.63,1513.27) 6995.36,1488.54 ; 7031.04,1590 cw(c7031.04,1571.08) v2@7044.42,1584.46 ; 7033.9,1590 ccw(c7033.9,1604.88) v2@7044.42,1594.36 ; v5(7297,838.58) 7298.52,838.58 v5@7297.76,839.34 ; v1(7457.52,3024.37) v1@7458.19,3025.04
